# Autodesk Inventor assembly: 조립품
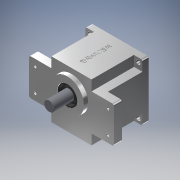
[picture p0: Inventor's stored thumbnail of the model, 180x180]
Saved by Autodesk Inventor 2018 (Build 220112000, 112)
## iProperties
Created: 2020-07
Part Number: 조립품
Material: 일반
Document SubType Name: Assembly
Designer: admin
Author: admin
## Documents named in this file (10)
- C:\Users\admin\Desktop\700707V1015\조립품.iam
- C:\Users\admin\Desktop\700707V1015\본체.ipt
- C:\Users\admin\Desktop\700707V1015\커버.ipt
- C:\Users\admin\Desktop\700707V1015\메인 축.ipt
- C:\Users\admin\Desktop\700707V1015\서브 축.ipt
- C:\Users\admin\Desktop\700707V1015\베어링 6003.ipt
- C:\Users\admin\Desktop\700707V1015\베어링 608.ipt
- C:\Users\admin\Desktop\700707V1015\볼트 M4.ipt
- C:\Users\admin\Desktop\700707V1015\오일 실 8 22 7.ipt
- C:\Users\admin\Desktop\700707V1015\오일 실 17 32 8.ipt
